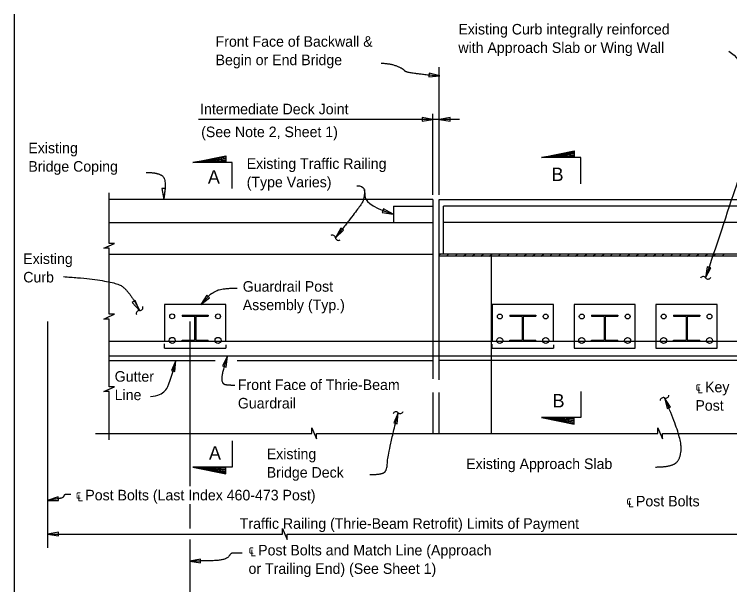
# Model space of a CAD drawing. Extents: x 21587 to 21656.3, y 56117.4 to 56157.3.
# Drawn here: x 21605.5 to 21619.15, y 56142.37 to 56153.26 of the extents above; entities that cross this region are included whole.
import ezdxf

# ---------------------------------------------------------------- set-up
doc = ezdxf.new("R2010")
doc.units = 0
for name, color, linetype in [('AdhocPoint_dp', 7, 'Continuous'), ('Border', 7, 'Continuous'), ('Patterning', 7, 'Continuous'), ('PlotBorder_dp', 7, 'Continuous'), ('SheetBorder_dp', 7, 'Continuous'), ('TextMisc', 7, 'Continuous')]:
    doc.layers.add(name, color=color, linetype=linetype)

msp = doc.modelspace()

# ---------------------------------------------------------------- linework, layer by layer
at = {"layer": 'AdhocPoint_dp'}
for p, q in [((21613.488, 56149.72), (21607.312, 56149.72)), ((21613.488, 56149.722), (21613.488, 56146.297)), ((21613.608, 56149.72), (21620.85, 56149.72)), ((21613.608, 56146.279), (21613.608, 56149.72)), ((21612.738, 56149.595), (21613.488, 56149.595)), ((21620.85, 56149.595), (21613.691, 56149.595)), ((21613.691, 56148.678), (21613.691, 56149.595)), ((21607.312, 56149.282), (21613.488, 56149.282)), ((21620.85, 56149.282), (21613.691, 56149.282)), ((21607.312, 56148.678), (21613.488, 56148.678)), ((21620.85, 56148.678), (21613.608, 56148.678)), ((21620.85, 56148.636), (21613.608, 56148.636)), ((21614.608, 56145.254), (21614.608, 56148.636)), ((21607.312, 56146.648), (21609.336, 56146.648)), ((21609.752, 56146.648), (21613.488, 56146.648)), ((21624.755, 56146.648), (21613.608, 56146.648)), ((21613.488, 56146.033), (21613.488, 56145.254)), ((21613.608, 56145.254), (21613.608, 56146.033))]:
    msp.add_line(p, q, dxfattribs=at)
msp.add_lwpolyline([(21612.738, 56149.595), (21612.738, 56149.282)], dxfattribs=at)
at = {"layer": 'Border'}
for p, q in [((21608.702, 56147.514), (21609.202, 56147.514)), ((21608.702, 56147.514), (21608.702, 56147.493)), ((21608.702, 56147.493), (21608.931, 56147.493)), ((21608.941, 56147.483), (21608.941, 56147.035)), ((21608.962, 56147.483), (21608.962, 56147.035)), ((21608.973, 56147.493), (21609.202, 56147.493)), ((21609.202, 56147.514), (21609.202, 56147.493)), ((21614.952, 56147.512), (21615.452, 56147.512)), ((21614.952, 56147.512), (21614.952, 56147.491)), ((21614.952, 56147.491), (21615.181, 56147.491)), ((21615.191, 56147.481), (21615.191, 56147.033)), ((21615.212, 56147.481), (21615.212, 56147.033)), ((21615.223, 56147.491), (21615.452, 56147.491)), ((21615.452, 56147.512), (21615.452, 56147.491)), ((21607.312, 56147.012), (21619.379, 56147.012)), ((21608.702, 56147.035), (21608.941, 56147.035)), ((21608.702, 56147.014), (21608.702, 56147.035)), ((21608.702, 56147.014), (21609.202, 56147.014)), ((21608.962, 56147.035), (21609.202, 56147.035)), ((21609.202, 56147.014), (21609.202, 56147.035)), ((21614.952, 56147.033), (21615.191, 56147.033)), ((21614.952, 56147.012), (21614.952, 56147.033)), ((21614.952, 56147.012), (21615.452, 56147.012)), ((21615.212, 56147.033), (21615.452, 56147.033)), ((21615.452, 56147.012), (21615.452, 56147.033)), ((21607.312, 56146.732), (21619.379, 56146.732))]:
    msp.add_line(p, q, dxfattribs=at)
for points in [[(21609.535, 56147.012), (21609.535, 56147.717), (21608.368, 56147.717), (21608.368, 56147.012)], [(21615.785, 56147.012), (21615.785, 56147.715), (21614.618, 56147.715), (21614.618, 56147.012)], [(21608.368, 56146.884), (21608.368, 56146.962)], [(21609.535, 56146.946), (21609.535, 56146.884)], [(21614.618, 56146.882), (21614.618, 56146.959)], [(21615.785, 56146.943), (21615.785, 56146.882)]]:
    msp.add_lwpolyline(points, dxfattribs=at)
for centre, radius in [((21608.514, 56147.488), 0.0469), ((21609.389, 56147.488), 0.0469), ((21614.764, 56147.486), 0.0469), ((21615.639, 56147.486), 0.0469), ((21608.514, 56147.03), 0.0573), ((21609.389, 56147.03), 0.0573), ((21614.764, 56147.028), 0.0573), ((21615.639, 56147.028), 0.0573)]:
    msp.add_circle(centre, radius, dxfattribs=at)
for centre, start, end in [((21608.931, 56147.483), 0, 90), ((21608.973, 56147.483), 90, 180), ((21615.181, 56147.481), 0, 90), ((21615.223, 56147.481), 90, 180)]:
    msp.add_arc(centre, 0.0104, start, end, dxfattribs=at)
at = {"layer": 'Patterning'}
for p, q in [((21616.514, 56147.512), (21617.014, 56147.512)), ((21616.514, 56147.512), (21616.514, 56147.491)), ((21616.514, 56147.491), (21616.743, 56147.491)), ((21616.754, 56147.481), (21616.754, 56147.033)), ((21616.775, 56147.481), (21616.775, 56147.033)), ((21616.785, 56147.491), (21617.014, 56147.491)), ((21617.014, 56147.512), (21617.014, 56147.491)), ((21618.077, 56147.512), (21618.577, 56147.512)), ((21618.077, 56147.512), (21618.077, 56147.491)), ((21618.077, 56147.491), (21618.306, 56147.491)), ((21618.316, 56147.481), (21618.316, 56147.033)), ((21618.337, 56147.481), (21618.337, 56147.033)), ((21618.348, 56147.491), (21618.577, 56147.491)), ((21618.577, 56147.512), (21618.577, 56147.491)), ((21616.514, 56147.033), (21616.754, 56147.033)), ((21616.514, 56147.012), (21616.514, 56147.033)), ((21616.514, 56147.012), (21617.014, 56147.012)), ((21616.775, 56147.033), (21617.014, 56147.033)), ((21617.014, 56147.012), (21617.014, 56147.033)), ((21618.077, 56147.033), (21618.316, 56147.033)), ((21618.077, 56147.012), (21618.077, 56147.033)), ((21618.077, 56147.012), (21618.577, 56147.012)), ((21618.337, 56147.033), (21618.577, 56147.033)), ((21618.577, 56147.012), (21618.577, 56147.033))]:
    msp.add_line(p, q, dxfattribs=at)
for points in [[(21617.348, 56146.882), (21617.348, 56147.715), (21616.181, 56147.715), (21616.181, 56146.882)], [(21618.91, 56146.882), (21618.91, 56147.715), (21617.743, 56147.715), (21617.743, 56146.882)], [(21608.368, 56146.884), (21609.535, 56146.884)], [(21614.618, 56146.882), (21615.785, 56146.882)], [(21616.181, 56146.882), (21617.348, 56146.882)], [(21617.743, 56146.882), (21618.91, 56146.882)]]:
    msp.add_lwpolyline(points, dxfattribs=at)
for centre, radius in [((21616.327, 56147.486), 0.0469), ((21617.202, 56147.486), 0.0469), ((21617.889, 56147.486), 0.0469), ((21618.764, 56147.486), 0.0469), ((21616.327, 56147.028), 0.0573), ((21617.202, 56147.028), 0.0573), ((21617.889, 56147.028), 0.0573), ((21618.764, 56147.028), 0.0573)]:
    msp.add_circle(centre, radius, dxfattribs=at)
for centre, start, end in [((21616.743, 56147.481), 0, 90), ((21616.785, 56147.481), 90, 180), ((21618.306, 56147.481), 0, 90), ((21618.348, 56147.481), 90, 180)]:
    msp.add_arc(centre, 0.0104, start, end, dxfattribs=at)
at = {"layer": 'PlotBorder_dp'}
for p, q in [((21605.502, 56153.256), (21605.502, 56127.317)), ((21613.61, 56149.808), (21613.61, 56152.243)), ((21613.488, 56149.808), (21613.488, 56151.352)), ((21613.996, 56151.248), (21609.019, 56151.248)), ((21615.559, 56150.521), (21616.184, 56150.631)), ((21616.184, 56150.618), (21615.559, 56150.521)), ((21615.559, 56150.521), (21616.184, 56150.601)), ((21608.91, 56150.429), (21609.535, 56150.539)), ((21609.535, 56150.526), (21608.91, 56150.429)), ((21608.91, 56150.429), (21609.535, 56150.509)), ((21609.535, 56150.491), (21608.91, 56150.429)), ((21608.91, 56150.429), (21609.535, 56150.473)), ((21609.535, 56150.453), (21608.91, 56150.429)), ((21616.184, 56150.583), (21615.559, 56150.521)), ((21615.559, 56150.521), (21616.184, 56150.564)), ((21616.184, 56150.544), (21615.559, 56150.521)), ((21608.858, 56144.246), (21608.858, 56147.393)), ((21616.184, 56145.532), (21615.559, 56145.556)), ((21615.559, 56145.556), (21616.184, 56145.512)), ((21616.184, 56145.494), (21615.559, 56145.556)), ((21615.559, 56145.556), (21616.184, 56145.476)), ((21616.184, 56145.459), (21615.559, 56145.556)), ((21615.559, 56145.556), (21616.184, 56145.446)), ((21609.535, 56144.586), (21608.91, 56144.609)), ((21608.91, 56144.609), (21609.535, 56144.566)), ((21609.535, 56144.547), (21608.91, 56144.609)), ((21608.91, 56144.609), (21609.535, 56144.529)), ((21609.535, 56144.512), (21608.91, 56144.609)), ((21608.91, 56144.609), (21609.535, 56144.499)), ((21608.858, 56143.438), (21608.858, 56143.901)), ((21608.858, 56135.158), (21608.858, 56143.226))]:
    msp.add_line(p, q, dxfattribs=at)
for points in [[(21613.62, 56152.078), (21613.416, 56152.134), (21613.409, 56152.064)], [(21613.488, 56151.248), (21613.28, 56151.283), (21613.28, 56151.212)], [(21613.611, 56151.248), (21613.819, 56151.212), (21613.819, 56151.283)], [(21608.352, 56149.721), (21608.388, 56149.93), (21608.317, 56149.93)], [(21612.73, 56149.441), (21612.543, 56149.539), (21612.521, 56149.472)], [(21611.628, 56148.989), (21611.785, 56149.131), (21611.73, 56149.175)], [(21618.687, 56148.227), (21618.787, 56148.413), (21618.72, 56148.435)], [(21609.059, 56147.715), (21609.226, 56147.844), (21609.174, 56147.892)], [(21607.893, 56147.6), (21607.806, 56147.793), (21607.748, 56147.754)], [(21608.584, 56146.646), (21608.498, 56146.453), (21608.566, 56146.435)], [(21609.572, 56146.73), (21609.474, 56146.543), (21609.541, 56146.521)], [(21617.907, 56145.933), (21617.953, 56145.727), (21618.018, 56145.753)], [(21612.824, 56145.649), (21612.739, 56145.455), (21612.808, 56145.438)], [(21606.137, 56143.974), (21606.348, 56143.971), (21606.337, 56144.041)], [(21606.135, 56143.332), (21606.343, 56143.297), (21606.343, 56143.368)], [(21608.848, 56142.816), (21609.056, 56142.781), (21609.056, 56142.851)]]:
    msp.add_lwpolyline(points, close=True, dxfattribs=at)
for points in [[(21616.309, 56150.021), (21616.309, 56150.521), (21615.559, 56150.521), (21616.184, 56150.646), (21616.184, 56150.521)], [(21609.66, 56149.929), (21609.66, 56150.429), (21608.91, 56150.429), (21609.535, 56150.554), (21609.535, 56150.429)], [(21607.312, 56148.322), (21607.312, 56148.791), (21607.208, 56148.791), (21607.312, 56148.836), (21607.415, 56148.881), (21607.312, 56148.881), (21607.312, 56149.85)], [(21607.312, 56146.575), (21607.312, 56147.438), (21607.208, 56147.438), (21607.312, 56147.483), (21607.415, 56147.528), (21607.312, 56147.528), (21607.312, 56148.322)], [(21607.312, 56145.128), (21607.312, 56146.056), (21607.208, 56146.056), (21607.312, 56146.101), (21607.415, 56146.146), (21607.312, 56146.146), (21607.312, 56147.019)], [(21616.309, 56146.056), (21616.309, 56145.556), (21615.559, 56145.556), (21616.184, 56145.431), (21616.184, 56145.556)], [(21607.053, 56145.254), (21611.175, 56145.254), (21611.175, 56145.357), (21611.22, 56145.254), (21611.265, 56145.15), (21611.265, 56145.254), (21613.496, 56145.254)], [(21613.496, 56145.254), (21617.776, 56145.254), (21617.776, 56145.357), (21617.821, 56145.254), (21617.866, 56145.15), (21617.866, 56145.254), (21620.131, 56145.254)], [(21609.66, 56145.109), (21609.66, 56144.609), (21608.91, 56144.609), (21609.535, 56144.484), (21609.535, 56144.609)], [(21606.135, 56143.332), (21610.618, 56143.332), (21610.618, 56143.436), (21610.663, 56143.332), (21610.708, 56143.229), (21610.708, 56143.332), (21626.014, 56143.332)]]:
    msp.add_lwpolyline(points, dxfattribs=at)
for centre, start, end in [((21611.569, 56148.981), 8.6098, 120.3371), ((21611.687, 56148.999), 188.6098, 300.3371), ((21618.64, 56148.188), 36.1618, 147.8891), ((21618.736, 56148.259), 216.1618, 327.8891), ((21607.888, 56147.54), 85.5858, 197.313), ((21607.897, 56147.659), 265.5858, 17.313), ((21617.931, 56145.987), 246.3072, 358.0344), ((21617.883, 56145.878), 66.3072, 178.0344), ((21612.782, 56145.605), 47.1839, 158.9112), ((21612.863, 56145.692), 227.1839, 338.9112)]:
    msp.add_arc(centre, 0.0596, start, end, dxfattribs=at)
for points, degree in [([(21619.131, 56152.551), (21619.433, 56152.384), (21619.657, 56151.348), (21619.596, 56150.833), (21619.344, 56150.232), (21618.879, 56148.789), (21618.687, 56148.227)], 3), ([(21612.498, 56152.323), (21612.683, 56152.316), (21612.921, 56152.217), (21612.954, 56152.158), (21613.224, 56152.118), (21613.62, 56152.078)], 2), ([(21608.02, 56150.237), (21608.232, 56150.237), (21608.418, 56150.106), (21608.352, 56149.721)], 2), ([(21612.185, 56149.909), (21612.182, 56149.749), (21612.108, 56149.595), (21611.628, 56148.989)], 2), ([(21612.039, 56149.979), (21612.19, 56149.988), (21612.169, 56149.796), (21612.239, 56149.6), (21612.73, 56149.441)], 3), ([(21606.44, 56148.247), (21607.434, 56148.18), (21607.731, 56147.911), (21607.893, 56147.6)], 2), ([(21609.756, 56148.023), (21609.438, 56148.02), (21609.254, 56147.914), (21609.225, 56147.896), (21609.059, 56147.715)], 2), ([(21608.098, 56145.956), (21608.251, 56145.97), (21608.387, 56146.054), (21608.464, 56146.177), (21608.584, 56146.646)], 3), ([(21609.71, 56146.169), (21609.579, 56146.172), (21609.477, 56146.192), (21609.454, 56146.369), (21609.572, 56146.73)], 2), ([(21617.736, 56144.612), (21618.039, 56144.612), (21618.224, 56144.782), (21618.221, 56145.206), (21617.907, 56145.933)], 2), ([(21612.287, 56144.468), (21612.541, 56144.468), (21612.619, 56144.588), (21612.619, 56144.821), (21612.824, 56145.649)], 2), ([(21606.578, 56144.089), (21606.513, 56144.089), (21606.449, 56144.082), (21606.439, 56144.025), (21606.313, 56144.001), (21606.137, 56143.974)], 2), ([(21609.851, 56142.968), (21609.731, 56142.968), (21609.632, 56142.968), (21609.59, 56142.887), (21609.456, 56142.827), (21609.01, 56142.816), (21608.848, 56142.816)], 2)]:
    msp.add_open_spline(points, degree=degree, dxfattribs=at)
at = {"layer": 'TextMisc'}
for p, q in [((21613.608, 56148.663), (21613.623, 56148.678)), ((21613.745, 56148.636), (21613.787, 56148.678)), ((21613.91, 56148.636), (21613.951, 56148.678)), ((21614.074, 56148.636), (21614.116, 56148.678)), ((21614.238, 56148.636), (21614.28, 56148.678)), ((21614.403, 56148.636), (21614.444, 56148.678)), ((21614.567, 56148.636), (21614.609, 56148.678)), ((21614.731, 56148.636), (21614.773, 56148.678)), ((21614.896, 56148.636), (21614.937, 56148.678)), ((21615.06, 56148.636), (21615.102, 56148.678)), ((21615.224, 56148.636), (21615.266, 56148.678)), ((21615.389, 56148.636), (21615.43, 56148.678)), ((21615.553, 56148.636), (21615.595, 56148.678)), ((21615.717, 56148.636), (21615.759, 56148.678)), ((21615.882, 56148.636), (21615.923, 56148.678)), ((21616.046, 56148.636), (21616.088, 56148.678)), ((21616.21, 56148.636), (21616.252, 56148.678)), ((21616.374, 56148.636), (21616.416, 56148.678)), ((21616.539, 56148.636), (21616.581, 56148.678)), ((21616.703, 56148.636), (21616.745, 56148.678)), ((21616.867, 56148.636), (21616.909, 56148.678)), ((21617.032, 56148.636), (21617.074, 56148.678)), ((21617.196, 56148.636), (21617.238, 56148.678)), ((21617.36, 56148.636), (21617.402, 56148.678)), ((21617.525, 56148.636), (21617.566, 56148.678)), ((21617.689, 56148.636), (21617.731, 56148.678)), ((21617.853, 56148.636), (21617.895, 56148.678)), ((21618.018, 56148.636), (21618.059, 56148.678)), ((21618.182, 56148.636), (21618.224, 56148.678)), ((21618.346, 56148.636), (21618.388, 56148.678)), ((21618.511, 56148.636), (21618.552, 56148.678)), ((21618.675, 56148.636), (21618.717, 56148.678)), ((21618.839, 56148.636), (21618.881, 56148.678)), ((21619.004, 56148.636), (21619.045, 56148.678)), ((21606.135, 56147.393), (21606.135, 56143.07))]:
    msp.add_line(p, q, dxfattribs=at)

# ---------------------------------------------------------------- texts
at = {"layer": 'PlotBorder_dp'}
for s, p in [('Existing Curb integrally reinforced ', (21613.973, 56152.87)), ('Front Face of Backwall &', (21609.342, 56152.636)), ('with Approach Slab or Wing Wall ', (21613.973, 56152.518)), ('Begin or End Bridge', (21609.342, 56152.284)), ('Existing ', (21605.77, 56150.603)), ('Bridge Coping ', (21605.77, 56150.251)), ('Existing Traffic Railing', (21609.935, 56150.304)), ('(Type Varies)', (21609.935, 56149.952)), ('Existing ', (21605.673, 56148.488)), ('Curb', (21605.673, 56148.136)), ('Guardrail Post ', (21609.86, 56147.959)), ('Assembly (Typ.)', (21609.86, 56147.607)), ('Gutter ', (21607.417, 56146.241)), ('Front Face of Thrie-Beam ', (21609.767, 56146.082)), ('℄ Key ', (21618.495, 56146.039)), ('Line', (21607.417, 56145.889)), ('Guardrail', (21609.767, 56145.73)), ('Post', (21618.495, 56145.687)), ('Existing ', (21610.318, 56144.761)), ('Bridge Deck', (21610.318, 56144.409)), ('℄ Post Bolts and Match Line (Approach ', (21609.97, 56142.924)), ('or Trailing End) (See Sheet 1)', (21609.97, 56142.572))]:
    msp.add_text(s, height=0.2016, dxfattribs=at).set_placement(p)
at = {"layer": 'SheetBorder_dp'}
for s, height, p in [('Intermediate Deck Joint', 0.2016, (21609.046, 56151.346)), ('(See Note 2, Sheet 1)', 0.2016, (21609.067, 56150.91)), ('B', 0.256, (21615.751, 56150.072)), ('B', 0.256, (21615.77, 56145.75)), ('Existing Approach Slab', 0.2016, (21614.122, 56144.573)), ('℄ Post Bolts (Last Index 460-473 Post)', 0.2016, (21606.673, 56143.975)), ('℄ Post Bolts', 0.2016, (21617.177, 56143.86)), ('Traffic Railing (Thrie-Beam Retrofit) Limits of Payment', 0.2016, (21609.803, 56143.432))]:
    msp.add_text(s, height=height, dxfattribs=at).set_placement(p)
for p in [(21609.195, 56150.023), (21609.216, 56144.754)]:
    msp.add_text('A', height=0.256, rotation=360, dxfattribs=at).set_placement(p)

doc.saveas('drawing.dxf')
